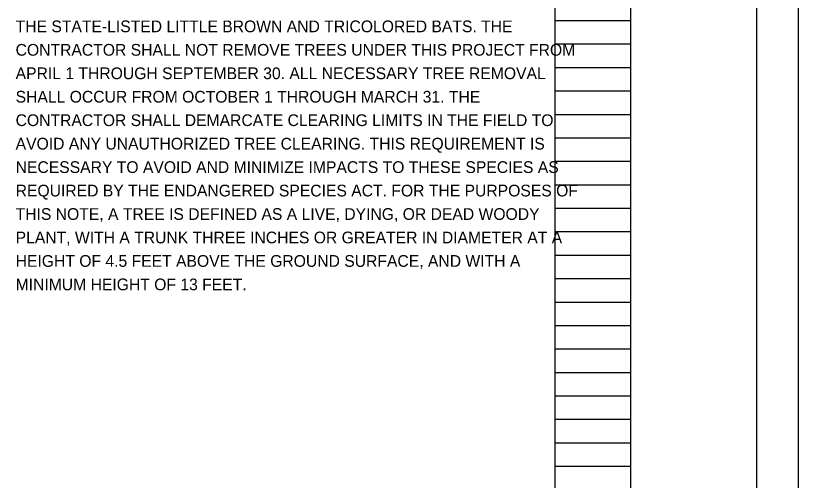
# Model space of a CAD drawing. Extents: x 0 to 34, y 0 to 22.
# Drawn here: x 24.66 to 34, y 5.57 to 11.12 of the extents above; entities that cross this region are included whole.
import ezdxf

# ---------------------------------------------------------------- set-up
doc = ezdxf.new("R2010")
doc.units = 0
for name, color, linetype in [('SH_Border', 7, 'Continuous'), ('SH_Cut_Line', 7, 'Continuous'), ('SH_Data', 7, 'Continuous'), ('SH_Text', 7, 'Continuous')]:
    doc.layers.add(name, color=color, linetype=linetype)

msp = doc.modelspace()

# ---------------------------------------------------------------- linework, layer by layer
at = {"layer": 'SH_Border'}
msp.add_line((32, 0.5), (32, 21.5), dxfattribs=at)
msp.add_lwpolyline([(1.5, 21.5), (33.5, 21.5), (33.5, 0.5), (1.5, 0.5)], close=True, dxfattribs=at)
at = {"layer": 'SH_Cut_Line'}
msp.add_lwpolyline([(0, 0), (34, 0), (34, 22), (0, 22)], close=True, dxfattribs=at)
at = {"layer": 'SH_Data'}
for p, q in [((31.1, 0.98), (31.1, 21.14)), ((32, 0.98), (32, 21.14)), ((31.1, 11.06), (32, 11.06)), ((31.1, 10.78), (32, 10.78)), ((31.1, 10.5), (32, 10.5)), ((31.1, 10.22), (32, 10.22)), ((31.1, 9.94), (32, 9.94)), ((31.1, 9.66), (32, 9.66)), ((31.1, 9.38), (32, 9.38)), ((31.1, 9.1), (32, 9.1)), ((31.1, 8.82), (32, 8.82)), ((31.1, 8.54), (32, 8.54)), ((31.1, 8.26), (32, 8.26)), ((31.1, 7.98), (32, 7.98)), ((31.1, 7.7), (32, 7.7)), ((31.1, 7.42), (32, 7.42)), ((31.1, 7.14), (32, 7.14)), ((31.1, 6.86), (32, 6.86)), ((31.1, 6.58), (32, 6.58)), ((31.1, 6.3), (32, 6.3)), ((31.1, 6.02), (32, 6.02)), ((31.1, 5.74), (32, 5.74))]:
    msp.add_line(p, q, dxfattribs=at)

# ---------------------------------------------------------------- texts
at = {"layer": 'SH_Text'}
for s, p in [('THE STATE-LISTED LITTLE BROWN AND TRICOLORED BATS. THE ', (24.66, 10.92)), ('CONTRACTOR SHALL NOT REMOVE TREES UNDER THIS PROJECT FROM ', (24.66, 10.64)), ('APRIL 1 THROUGH SEPTEMBER 30. ALL NECESSARY TREE REMOVAL ', (24.66, 10.36)), ('SHALL OCCUR FROM OCTOBER 1 THROUGH MARCH 31. THE ', (24.66, 10.08)), ('CONTRACTOR SHALL DEMARCATE CLEARING LIMITS IN THE FIELD TO ', (24.66, 9.8)), ('AVOID ANY UNAUTHORIZED TREE CLEARING. THIS REQUIREMENT IS ', (24.66, 9.52)), ('NECESSARY TO AVOID AND MINIMIZE IMPACTS TO THESE SPECIES AS ', (24.66, 9.24)), ('REQUIRED BY THE ENDANGERED SPECIES ACT. FOR THE PURPOSES OF ', (24.66, 8.96)), ('THIS NOTE, A TREE IS DEFINED AS A LIVE, DYING, OR DEAD WOODY ', (24.66, 8.68)), ('PLANT, WITH A TRUNK THREE INCHES OR GREATER IN DIAMETER AT A ', (24.66, 8.4)), ('HEIGHT OF 4.5 FEET ABOVE THE GROUND SURFACE, AND WITH A ', (24.66, 8.12)), ('MINIMUM HEIGHT OF 13 FEET.', (24.66, 7.84))]:
    msp.add_text(s, height=0.14, dxfattribs=at).set_placement(p)

doc.saveas('drawing.dxf')
